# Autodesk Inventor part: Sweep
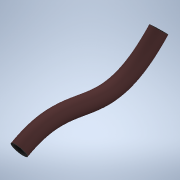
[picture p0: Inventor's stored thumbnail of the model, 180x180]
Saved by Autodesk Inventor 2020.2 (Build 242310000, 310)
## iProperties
Created: 2019-12
Part Number: Sweep
Material: Rubber, Silicone
Document SubType Name: Modeling
Designer: Synergysoft Dell02
Density: 1.25 g/cm^3
Appearance: Rubber - Black
Author: Synergysoft Dell02
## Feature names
1. Sweep1
2. Shell1
## Parameters: d1 = 0, d2 = 0, d3 = 1 mm
